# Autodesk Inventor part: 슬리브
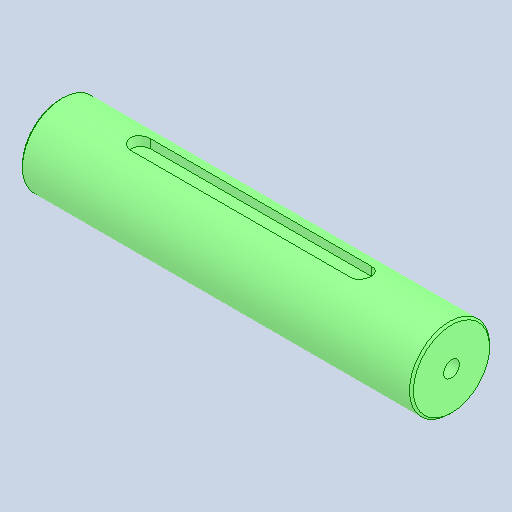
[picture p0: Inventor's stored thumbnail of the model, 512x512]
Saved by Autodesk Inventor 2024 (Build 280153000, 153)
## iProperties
Created: 2024-08
Part Number: 슬리브
Material: 일반
Document SubType Name: Modeling
Designer: user
Density: 1 g/cm^3
Appearance: 기본값
Author: jhkim
Sending System: Autodesk Inventor 2025
Preprocessor: ST-DEVELOPER v20
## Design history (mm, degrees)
feature "솔리드1"
node "솔리드2"
